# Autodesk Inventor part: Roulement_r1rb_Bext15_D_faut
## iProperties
Created: 2011-10
Part Number: Roulement_r1rb_Bext15_D_faut
Document SubType Name: Modeling
Designer: Bruno
Author: Bruno
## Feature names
1. Base1
